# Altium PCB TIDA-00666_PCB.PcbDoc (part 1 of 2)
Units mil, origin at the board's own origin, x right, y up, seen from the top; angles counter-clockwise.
Board outline 1800 x 1650 mil, 4 copper layers (Layer 1 - Top Layer, Layer 2 - GND, Layer 3 - POWER, Layer 4 - Bottom Layer), stack 61.4 mil thick; 112 components, 67 nets, 298 pads, 149 vias.
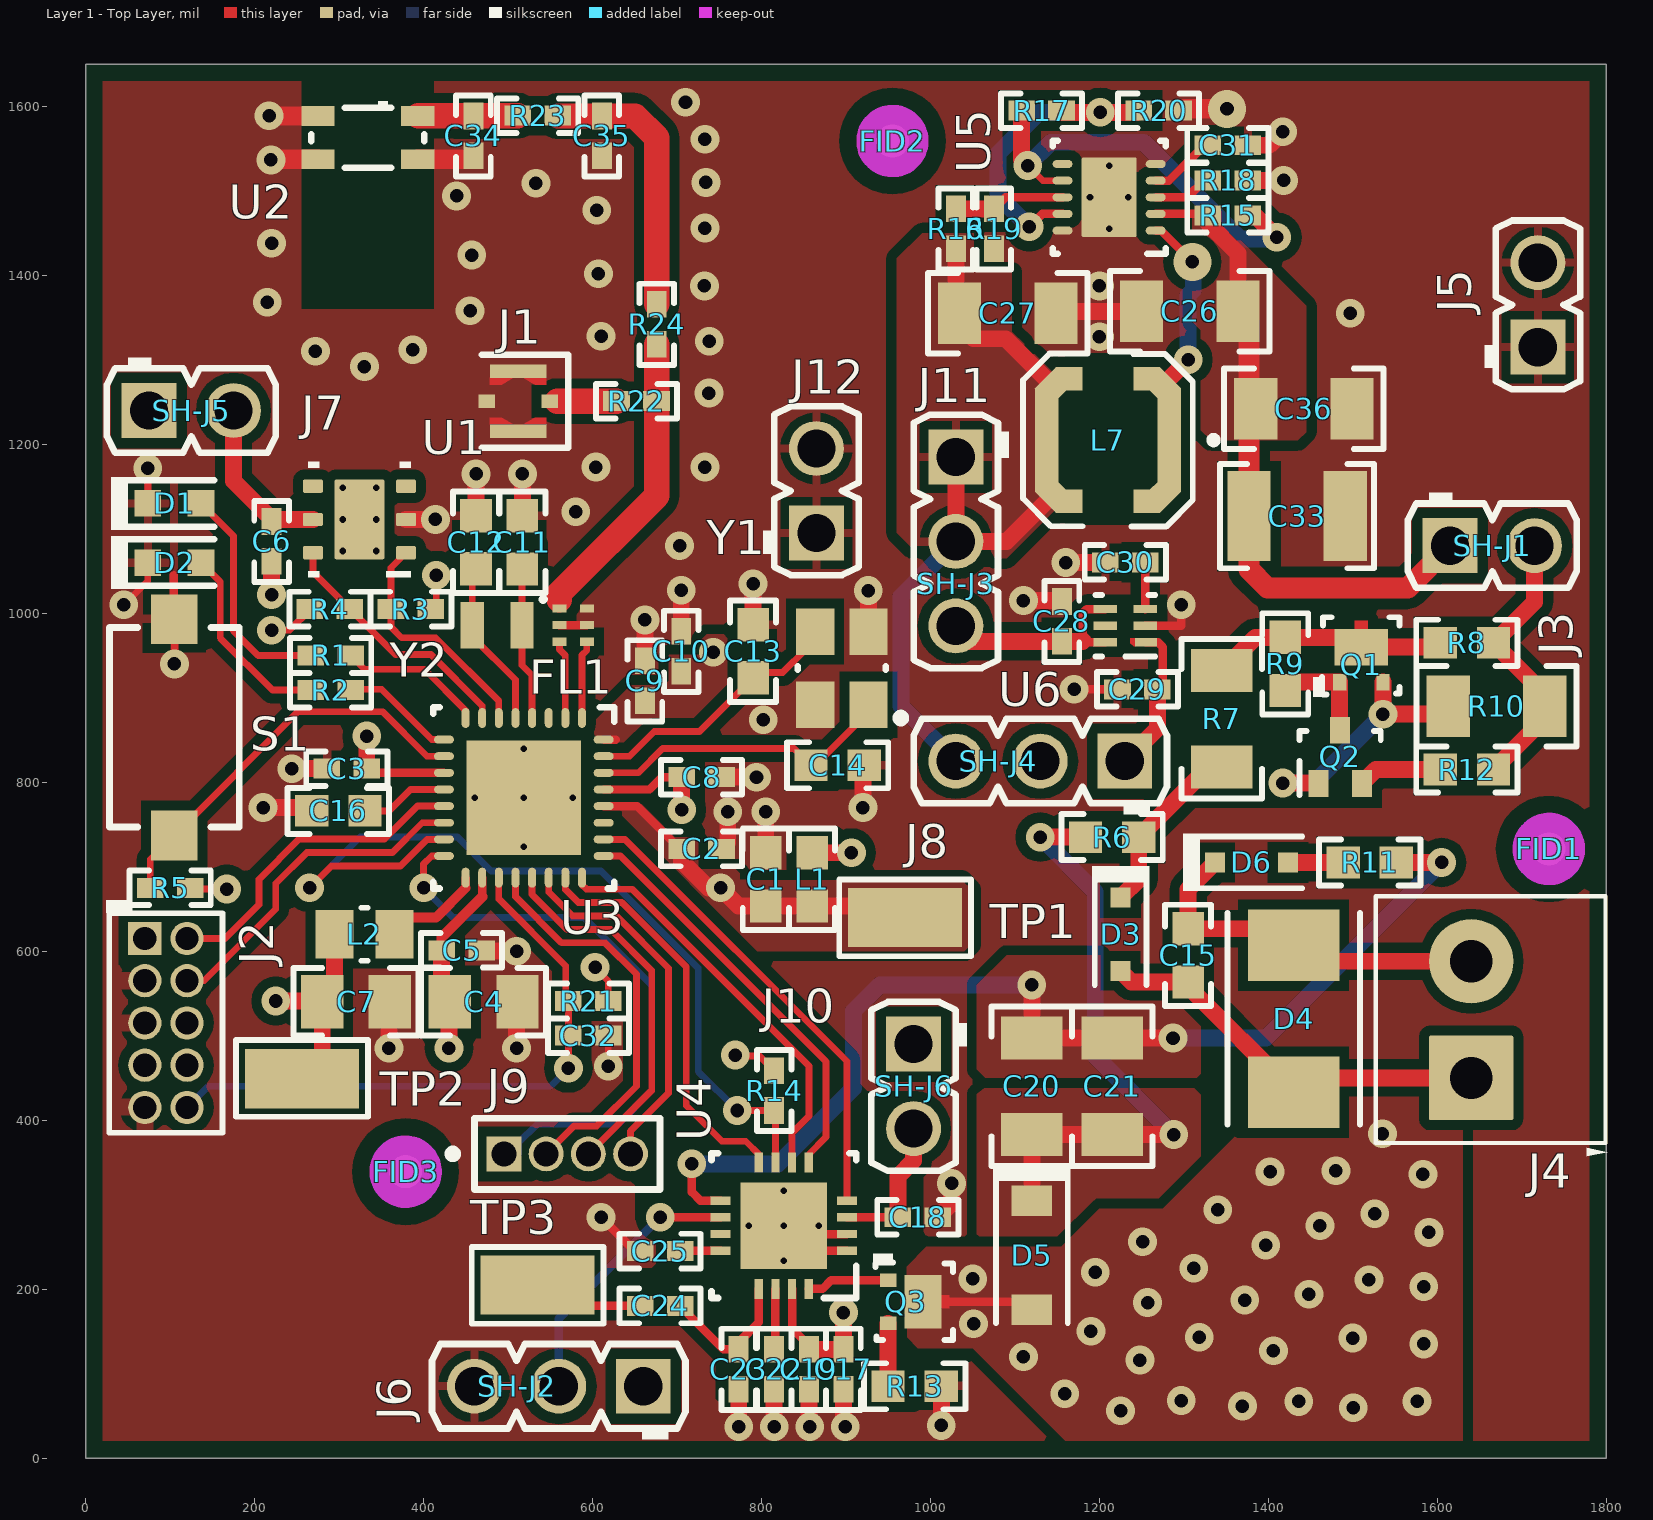
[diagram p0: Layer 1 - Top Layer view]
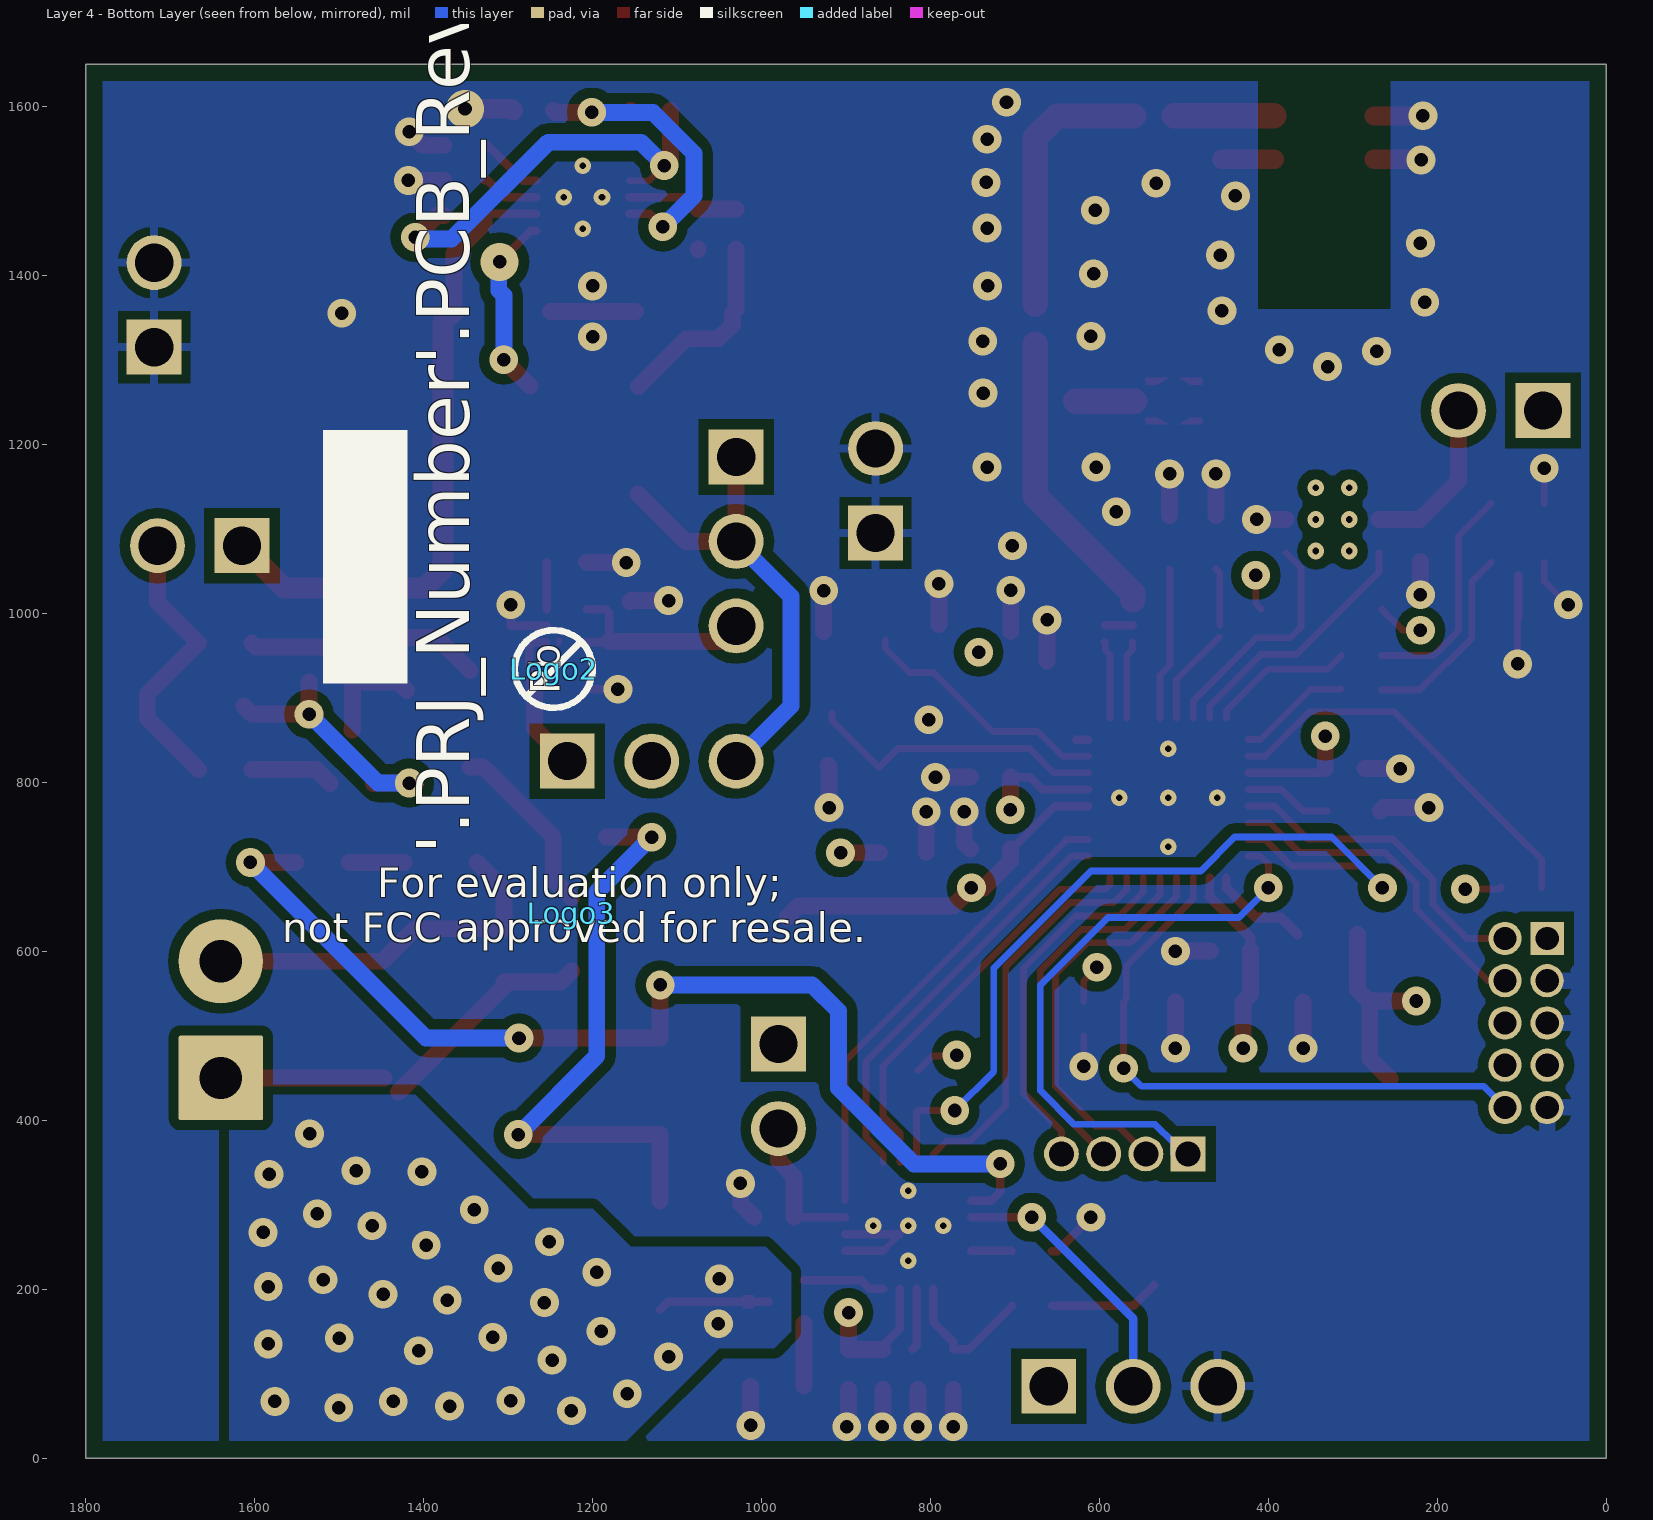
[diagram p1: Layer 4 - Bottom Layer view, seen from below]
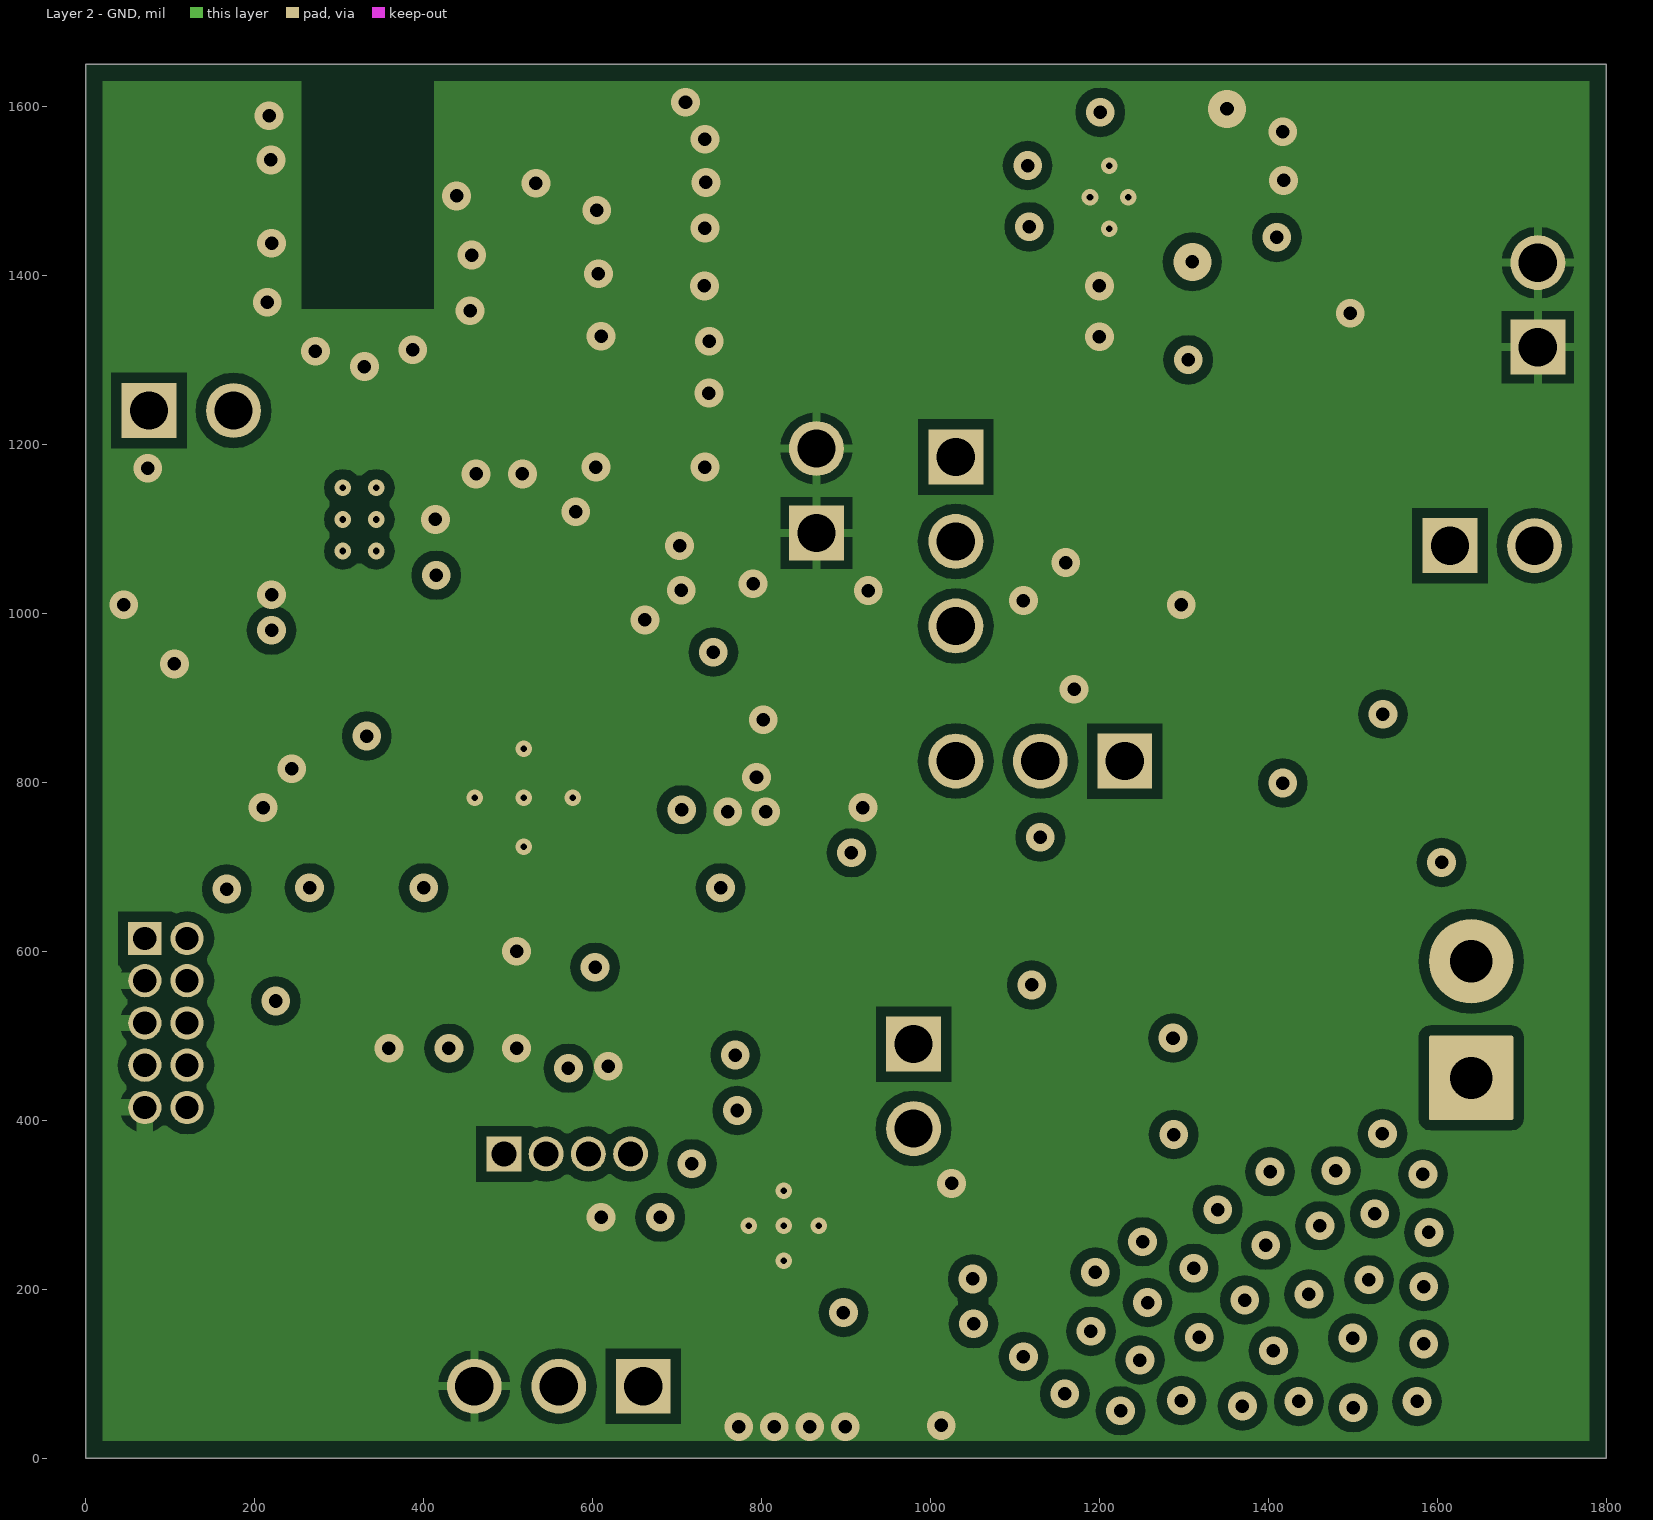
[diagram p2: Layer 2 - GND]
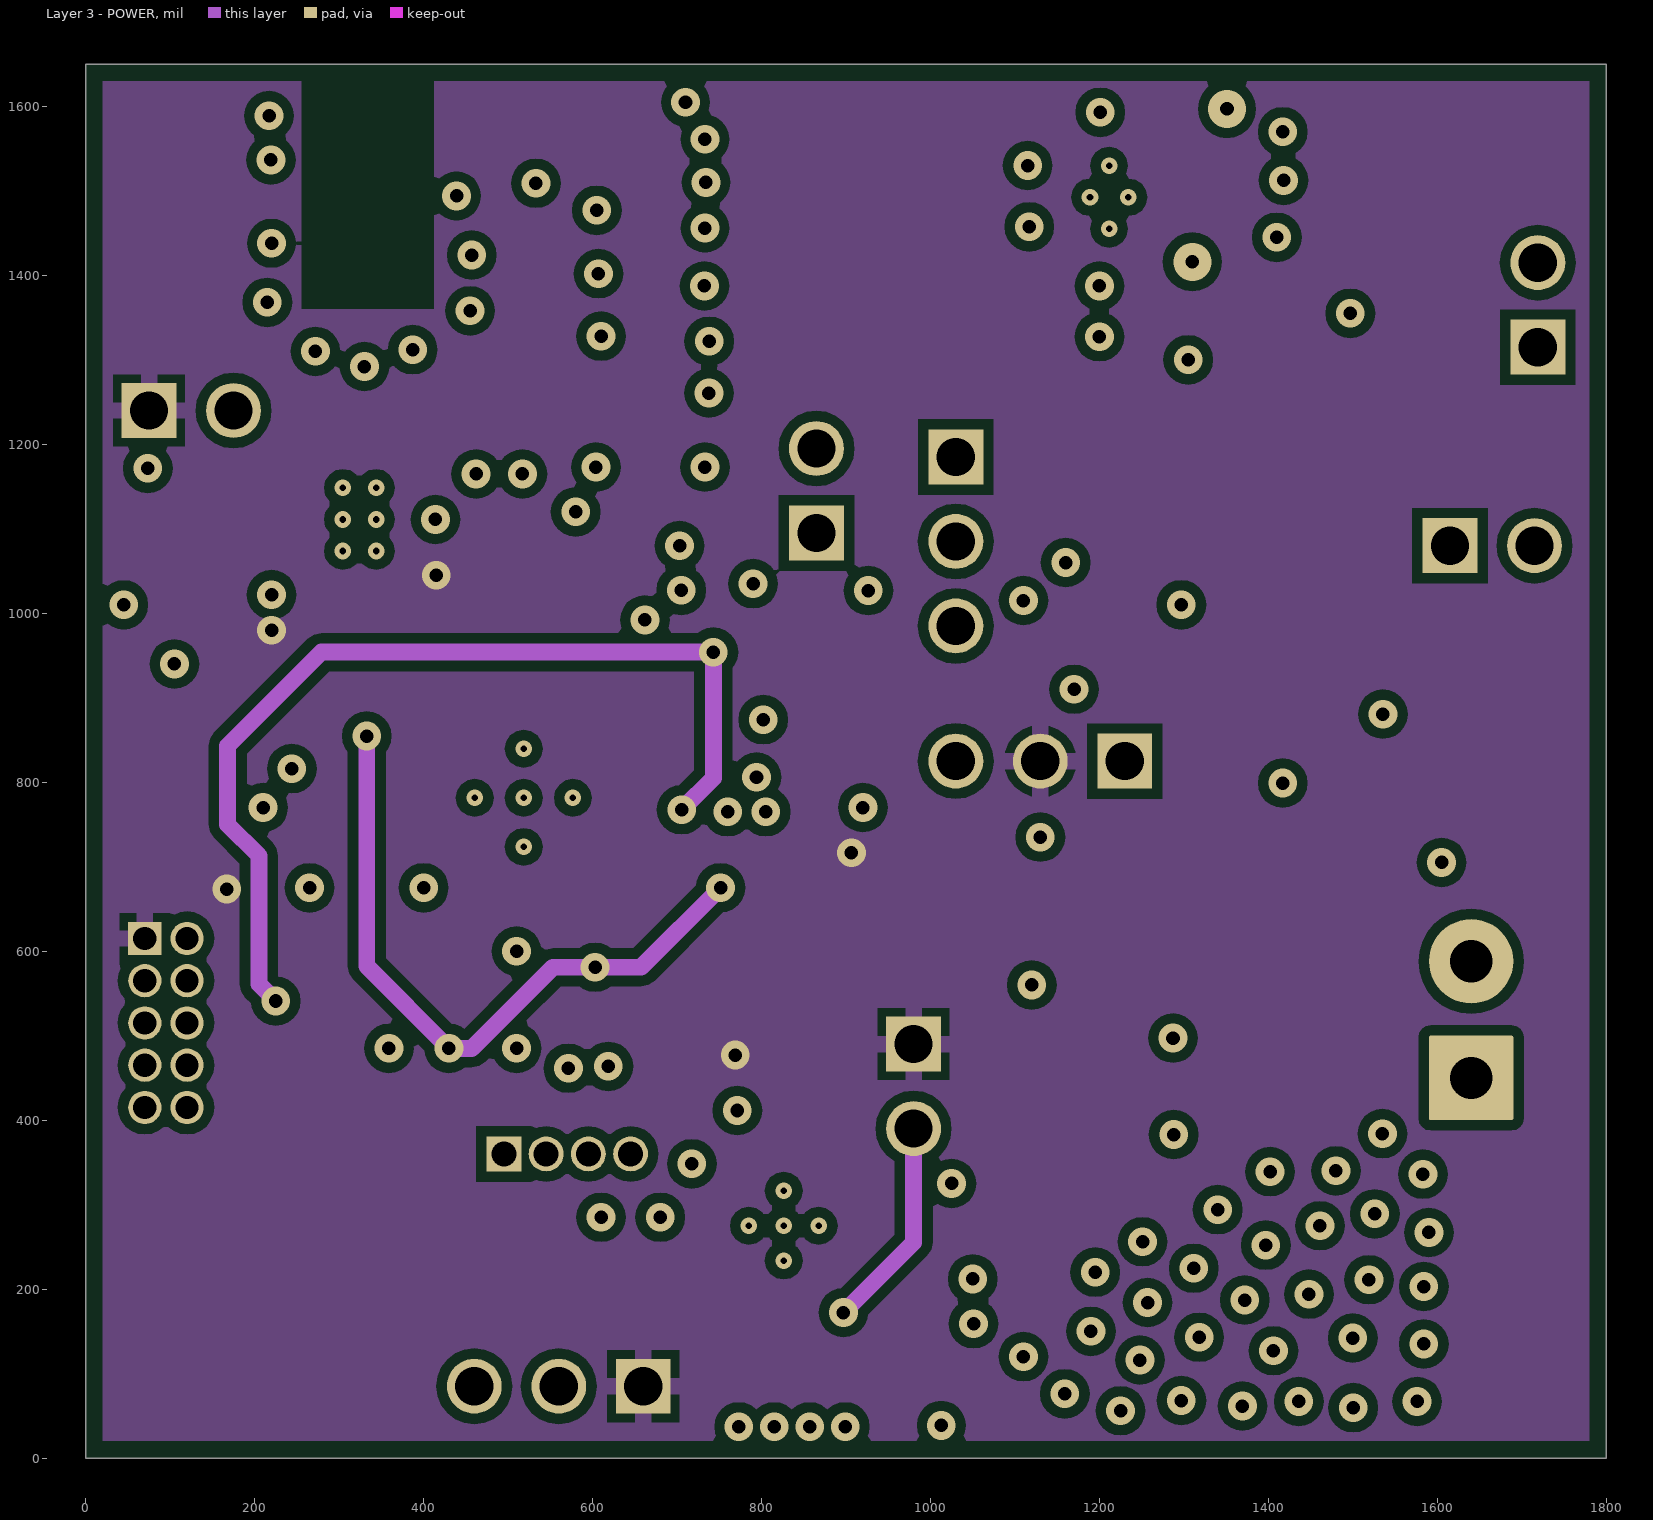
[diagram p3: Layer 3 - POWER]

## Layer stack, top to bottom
Top Solder: solder mask 0.4, Solder Resist, Dk 3.5
Layer 1 - Top Layer: signal copper 1.4
Dielectric1: prepreg 18.6, 370HR, Dk 4.2
Layer 2 - GND: signal copper 1.4
Dielectric3: core 18.6, 370HR, Dk 4.2
Layer 3 - POWER: signal copper 1.4
Dielectric2: prepreg 18.6, 370HR, Dk 4.2
Layer 4 - Bottom Layer: signal copper 1.4
Bottom Solder: solder mask 0.4, Solder Resist, Dk 3.5

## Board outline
0,0 0,1650 1800,1650 1800,0

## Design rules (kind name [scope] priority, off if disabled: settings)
AcuteAngle [All] p1: minimum=4.50000000000000E+0001 checktracksonly=FALSE
AssemblyTestPointUsage [All] p1: valid=2
BoardOutlineClearance BoardOutlineClearance_MountingHoles [OnCopper and InComponentClass('Mounting Holes')] p1: gap=22
BoardOutlineClearance BoardOutlineClearance_Poly [OnCopper and InPoly] p2: gap=20
BoardOutlineClearance [OnCopper and Not InComponentClass('Logo') and not InComponentClass('FiducialMark') and not InRegion(1000,500,4000,800)] p3: gap=20
Clearance Clearance_Keepouts [((IsTrack Or IsArc) And Not InPoly) And IsFree and IsKeepOut vs ((IsTrack Or IsArc) And Not InPoly) And IsFree and IsKeepOut] p1: gap=0
Clearance Clearance_BoardEdge_Poly [OnCopper and InPoly vs IsKeepOut] p2: gap=20
Clearance Clearance_BoardEdge [OnCopper and Not InComponentClass('Logo') and not InComponentClass('FiducialMark') and not InRegion(1000,500,4000,800)and Not IsKeepout vs IsKeepOut] p3: gap=25 except(4: SMDPad-Fill)
Clearance Clearance_Poly [InPolygon] p4: gap=12
Clearance [All] p5: gap=7.87
ComponentClearance ComponentClearance_Header [InComponent('J3') vs InComponent('J5')] p1: gap=10 collisioncheckmode=3 verticalgap=10 showdistances=FALSE
ComponentClearance ComponentClearance_MountingHoles_FiducialMarks [InComponentClass('Mounting Holes') vs InComponentClass('FiducialMark')] p2: gap=40 collisioncheckmode=3 verticalgap=10 showdistances=FALSE
ComponentClearance ComponentClearance_Shunt [InComponentClass('Header') vs InComponentClass('Shunt')] p3: gap=0 collisioncheckmode=3 verticalgap=0 showdistances=FALSE
ComponentClearance ComponentClearance_Logo [InComponentClass('Logo')] p4: gap=10 collisioncheckmode=3 verticalgap=10 showdistances=FALSE
ComponentClearance ComponentClearance_ScrewToNut [(HasFootprint('NY PMS 440 0025 PH')) vs (HasFootprint('Keystone_1902C'))] p5: gap=5 collisioncheckmode=3 verticalgap=10 showdistances=FALSE
ComponentClearance ComponentClearance_MountingHoles [InComponentClass('Mounting Holes')] p6: gap=10 collisioncheckmode=3 verticalgap=100000 showdistances=FALSE
ComponentClearance ComponentClearance_SmallPassives [HasFootprint('0201*') or HasFootprint('0402*') or HasFootprint('0508') or HasFootprint('0603*') or HasFootprint('0612') or HasFootprint('0805*') or HasFootprint('0815*') or HasFootprint('0830*') or HasFootprint('1206*') or HasFootprint('1210*') or HasFootprint('1808*') or HasFootprint('1812*') or HasFootprint('1825*') or HasFootprint('2010*') or HasFootprint('2220*') or HasFootprint('2225*') or HasFootprint('2512*') or HasFootprint('2728*') or HasFootprint('3518*') vs HasFootprint('0201*') or HasFootprint('0402*') or HasFootprint('0508') or HasFootprint('0603*') or HasFootprint('0612') or HasFootprint('0805*') or HasFootprint('0815*') or HasFootprint('0830*') or HasFootprint('1206*') or HasFootprint('1210*') or HasFootprint('1808*') or HasFootprint('1812*') or HasFootprint('1825*') or HasFootprint('2010*') or HasFootprint('2220*') or HasFootprint('2225*') or HasFootprint('2512*') or HasFootprint('2728*') or HasFootprint('3518*')] p7: gap=14.96 collisioncheckmode=3 verticalgap=10 showdistances=FALSE
ComponentClearance ComponentClearance_THtoSMT [IsThruComponent vs IsSMTComponent] p8: gap=20 collisioncheckmode=3 verticalgap=10 showdistances=FALSE
ComponentClearance ComponentClearance_THtoTH [IsThruComponent vs IsThruComponent] p9: gap=40 collisioncheckmode=3 verticalgap=10 showdistances=FALSE
ComponentClearance [All] p10: gap=30 collisioncheckmode=3 verticalgap=10 showdistances=FALSE
DiffPairsRouting [All] p1: maxlimit=100 minlimit=10 mostfreqgap=10 toplayer_minwidth=15 toplayer_maxwidth=15 toplayer_prefwidth=15 midlayer1_minwidth=15 midlayer1_maxwidth=15 midlayer1_prefwidth=15 midlayer2_minwidth=15 midlayer2_maxwidth=15 midlayer2_prefwidth=15 bottomlayer_minwidth=15 bottomlayer_maxwidth=15 bottomlayer_prefwidth=15 maxuncoupledlength=1000
FabricationTestPointUsage TestPointUsage [All] p1: valid=2 allowmultiple=FALSE
FabricationTestpoint Testpoint [All] p1: side=3 testpointundercomponent=TRUE minsize=40 maxsize=100 preferedsize=60 minholesize=0 maxholesize=40 preferedholesize=32 testpointgrid=1 allowsidetop=TRUE allowsidebottom=TRUE usegrid=TRUE gridtolerance=0.01
FanoutControl Fanout_LCC [IsLCC] p1: bgadir=Out bgaviamode=Centered fanoutstyle=Auto fanoutdirection=Alternating viagrid=1 // Fanout_LCC (Default Rule)
FanoutControl Fanout_BGA [IsBGA] p2: bgadir=Out bgaviamode=Centered fanoutstyle=Auto fanoutdirection=Alternating viagrid=1 // Fanout_BGA (Default Rule)
FanoutControl Fanout_Default [All] p4: bgadir=Out bgaviamode=Centered fanoutstyle=Auto fanoutdirection=Alternating viagrid=1 // Fanout_Default (Default Rule)
FanoutControl Fanout_Small [(CompPinCount < 5)] p5: bgadir=Out bgaviamode=Centered fanoutstyle=Auto fanoutdirection=OutThenIn viagrid=1 // Fanout_Small (Default Rule)
HoleSize [All] p1: absolutevalues=TRUE maxlimit=251 minlimit=7.87 maxpercent=80.000 minpercent=20.000
MinimumAnnularRing MinimumAnnularRing_ThermalPad [IsVia and InAnyComponent] p1: minimumring=5.9
MinimumAnnularRing MinimumAnnularRing_J9_J2 [HasPad('J9-*') or HasPad('J2-*')] p2: minimumring=5.9
MinimumAnnularRing [All] p3: minimumring=8
MinimumSolderMaskSliver MinimumSolderMaskSliver_Logo [InComponentClass('Logo') vs InComponentClass('Logo')] p1: minsoldermaskwidth=0.7
MinimumSolderMaskSliver [All] p2: minsoldermaskwidth=3.94
PlaneConnect [All] p1: planeconnectstyle=Direct reliefexpansion=10 reliefentries=4 reliefconductorwidth=10 reliefairgap=10
PolygonConnect PolygonConnect_vccSENSOR [InNet('VCC_SENSOR') vs IsThruPin] p1: connectstyle=Relief reliefconductorwidth=20 reliefentries=4 polygonreliefangle="90 Angle" airgapwidth=10
PolygonConnect PolygonConnect_J2 [All vs InComponent('J2')] p2: connectstyle=Relief reliefconductorwidth=20 reliefentries=4 polygonreliefangle="90 Angle" airgapwidth=10
PolygonConnect PolygonConnect_THT [IsThruPin] p3: connectstyle=Relief reliefconductorwidth=10 reliefentries=4 polygonreliefangle="90 Angle" airgapwidth=10
PolygonConnect PolygonConnect_SMD [InPadClass('PolySMD')] p4: connectstyle=Relief reliefconductorwidth=10 reliefentries=4 polygonreliefangle="90 Angle" airgapwidth=10
PolygonConnect [All] p5: connectstyle=Direct reliefconductorwidth=10 reliefentries=4 polygonreliefangle="90 Angle" airgapwidth=10
RoutingVias ThermalPadVias [IsVia and InAnyComponent] p1: holewidth=7.87 width=19.68 viastyle="Through Hole" minholewidth=7.87 minwidth=19.68 maxholewidth=12.99 maxwidth=23.62
RoutingVias [All] p2: holewidth=16 width=34 viastyle="Through Hole" minholewidth=7.87 minwidth=26 maxholewidth=40 maxwidth=65
ShortCircuit ShortCircuit_ThermalVIA [IsVia vs HasPad('U1-7')] p1: allowed=TRUE
ShortCircuit [All] p2: allowed=FALSE
SilkToBoardRegionClearance [Not ((IsComment or IsDesignator) And (Hide <> 'False')) and not InRegion(1000,500,4000,800)] p1:
SilkToSilkClearance SilkToSilkClearance_Pb-FreeLogo [(HasFootprint('Pb-Free_Overlay_Medium') OR HasFootprint('Pb-Free_Overlay_Small')) vs (HasFootprint('Pb-Free_Overlay_Medium') OR HasFootprint('Pb-Free_Overlay_Small'))] p1: silktosilkclearance=0
SilkToSilkClearance [All] p2: silktosilkclearance=4
SilkToSolderMaskClearance SilkToComponentPadClearance [IsPad and InAnycomponent] p1: minsilkscreentomaskgap=5 clearancetoexposedcopper=TRUE
SilkToSolderMaskClearance "Silk to Solder Mask Opening" [IsPad] p2: minsilkscreentomaskgap=1 clearancetoexposedcopper=TRUE
SolderMaskExpansion [All] p1: expansion=1.97
Width [All] p1: maxlimit=100 minlimit=6 preferedwidth=10 checkconnectedcopper=TRUE
14 further rules are at their usual default settings.

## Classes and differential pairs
component class TIDA-00666_Hardware: FID1 FID2 FID3 Logo2 Logo3 ZZ1 ZZ2 ZZ3 ZZ4
component class FiducialMark: FID1 FID2 FID3
component class AssemblyNote: ZZ1 ZZ2 ZZ3 ZZ4
component class Header: J2 J3 J5 J6 J7 J8 J9 J10 J11 J12
component class Shunt: SH-J1 SH-J2 SH-J3 SH-J4 SH-J5 SH-J6
component class TIDA-00666_DAC: C15 C17 C18 C19 C20 C21 C22 C23 C24 C25 D3 D4 D5 D6 J3 J4 J5 J6 J10 Q1 Q2 Q3 R6 R7 R8 R9 R10 R11 R12 R13 R14 SH-J1 SH-J2 SH-J6 TP3 U4
component class TIDA-00666_MCU: C1 C2 C3 C4 C5 C6 C7 C8 C9 C10 C11 C12 C13 C14 C16 C32 C34 C35 D1 D2 FL1 J1 J2 J7 J9 L1 L2 R1 R2 R3 R4 R5 R21 R22 R23 R24 S1 SH-J5 TP1 TP2 U1 U2 U3 Y1 Y2
component class TIDA-00666_Power: C26 C27 C28 C29 C30 C31 C33 C36 J8 J11 J12 L7 R15 R16 R17 R18 R19 R20 SH-J3 SH-J4 U5 U6
pad class PolySMD: C3-2 C11-1 C12-2 C13-2 C14-2 C16-2 C29-2 C30-2 C31-2 D1-1 D2-1 R13-1 R18-1 S1-2

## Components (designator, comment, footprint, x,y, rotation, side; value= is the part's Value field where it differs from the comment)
C1 "Used in BOM report" 0603 805,685 r90 top
C2 "GRM155R70J104KA01D" 0402 729.06,721.02 r0 top
C3 "GRM155R70J104KA01D" 0402 309.05,816.02 r180 top
C4 "GRM21BR70J106KE76L" 0805_HV 471,540 r0 top
C5 "GRM155R70J104KA01D" 0402 445,601 r0 top
C6 "GRM155R70J104KA01D" 0402 220,1085 r270 top
C7 "GRM21BR70J106KE76L" 0805_HV 320,540 r0 top
C8 "GRM155R70J104KA01D" 0402 729.06,806.02 r0 top
C9 "GRM155R70J104KA01D" 0402 662,920 r90 top
C10 "Used in BOM report" 0402 705,955 r90 top
C11 "06035A120JAT2A" 0603 517,1084 r270 top
C12 "06035A120JAT2A" 0603 462.06,1084.02 r90 top
C13 "Used in BOM report" 0603 790,955 r90 top
C14 "Used in BOM report" 0603 890,820 r0 top
C15 "C1608X7R2A103K" 0603 1305,595 r90 top
C16 "GRM188R70J105KA01D" 0603 299.05,766.02 r180 top
C17 "C1005X5R1C225K050BC" 0402 897,105 r270 top
C18 "C1005X5R0J104K" 0402 985,285 r0 top
C19 "C1005X5R0J104K" 0402 856,105 r270 top
C20 "12061C104JAT2A" 1206 1120,440 r90 top
C21 "GRM31CR72A105KA01L" 1206 1215,440 r90 top
C22 "GRM155R61A394KE15D" 0402 815,105 r270 top
C23 "GRM155R60J224KE01D" 0402 773,105 r270 top
C24 "GRM155R71E682KA01D" 0402 680,180 r180 top
C25 "GRM155R60J102KA01D" 0402 680,245 r180 top
C26 "GRM31CR72A105KA01L" 1206 1306.96,1357.4 r180 top
C27 "GRM31CR71A226KE15L" 1206 1091.46,1355 r0 top
C28 "C1005X7S1A105K050BC" 0402 1155.59,990.32 r90 top
C29 "C1005X7S1A105K050BC" 0402 1245,910 r180 top
C30 "C1005X7R1C103K050BA" 0402 1230.59,1060.32 r180 top
C31 "GRM155R71C473KA01D" 0402 1352,1554 r0 top
C32 "GRM155R70J104KA01D" 0402 595,500 r0 top
C33 "GRM32ER71J106KA12L" 1210_270 1434,1115 r0 top
C34 "Used in BOM report" 0402 459,1565 r270 top
C35 "Used in BOM report" 0402 611,1565 r270 top
C36 "UMK316B7225KL-T" 1206 1442,1242 r0 top
D1 "150060VS75000" WL-SMCW_GREEN 105,1130 r0 top
D2 "150060SS75000" WL-SMCW_RED 105,1060 r0 top
D3 "BAT46WJ,115" SOD-323F 1225,620 r270 top
D4 "SM6T39CA" SMB-Bi 1430,520 r90 top
D5 "MMSZ4686T1G" SOD-123 1120,240 r270 top
D6 "BAT46WJ,115" SOD-323F 1380,705 r0 top
FID1 "Fiducial" Fiducial10-20 1732,721 r0 top
FID2 "Fiducial" Fiducial10-20 955,1559 r0 top
FID3 "Fiducial" Fiducial10-20 378.68,338.96 r0 top
FL1 "LFB182G45BG5D920" Murata_LFB182G45BG5D920 577,986.02 r0 top
J1 "MM5829-2700RJ4" MuRata_MM5829-2700 512,1251 r270 top
J2 "GRPB052VWVN-RC" CONN_GRPB052VWVN-RC 95,515 r270 top
J3 "61300211121" WURTH_61300211121 1665,1080 r0 top
J4 "ED555/2DS" TERM_BLK_ED555-2DS 1640,450 r90 top
J5 "61300211121" WURTH_61300211121 1719,1365 r90 top
J6 "61300311121" WURTH_61300311121 560,85 r180 top
J7 "61300211121" WURTH_61300211121 125,1240 r0 top
J8 "61300311121" WURTH_61300311121 1130,825 r180 top
J9 "GRPB041VWVN-RC" Sullins_GRPB041VWVN-RC 570,360 r0 top
J10 "61300211121" WURTH_61300211121 980,440 r270 top
J11 "61300311121" WURTH_61300311121 1030,1085 r270 top
J12 "61300211121" WURTH_61300211121 865,1145 r90 top
L1 "BLM18HE152SN1D" 0603 860,685 r90 top
L2 "CKS2125100M-T" 0805_145 330,620 r180 top
L7 "LPS4018-184MLB" LPS4018 1210,1205 r180 top
Logo2 "Pb-Free Symbol" Pb-Free_Overlay_Small 1246,934 r90 bottom
Logo3 "FCC disclaimer" FCC_disclaimer_stacked 1225,645 r180 bottom
Q1 "BC55-16PA,115" SOT1061 1510,950 r90 top
Q2 "MMSTA06-7-F" SOT-323 1485,830 r90 top
Q3 "BC55-16PA,115" SOT1061 981.34,185 r0 top
R1 "CRCW0402470RJNED" 0402 290,950 r0 top
R2 "CRCW0402470RJNED" 0402 290,909 r180 top
R3 "CRCW040210K0FKED" 0402 385,1005 r0 top
R4 "CRCW040210K0FKED" 0402 289,1005 r180 top
R5 "CRCW040247K5FKED" 0402 100,675 r0 top
R6 "CRCW06030000Z0EA" 0603 1215,735 r180 top
R7 "CRCW1206200RFKEA" 1206 1345,875 r90 top
R8 "CRCW06030000Z0EA" 0603 1635,965 r0 top
R9 "CRCW060324K9FKEA" 0603 1420,940 r90 top
R10 "CRCW120649R9FKEA" 1206 1670,890 r180 top
R11 "CRCW06030000Z0EA" 0603 1520,705 r180 top
R12 "CRCW0603100RFKEA" 0603 1635,815 r180 top
R13 "CRCW060320R0FKEA" 0603 981.34,85 r180 top
R14 "CRCW04021M00JNED" 0402 815,435 r270 top
R15 "CRCW04022M00FKED" 0402 1352,1471 r180 top
R16 "CRCW0402499KFKED" 0402 1030,1455 r270 top
R17 "CRCW0402357KFKED" 0402 1131.46,1595 r180 top
R18 "CRCW0402100KFKED" 0402 1351.96,1512.4 r180 top
R19 "CRCW0402294KFKED" 0402 1075,1455 r90 top
R20 "CRCW040234K0FKED" 0402 1270,1595 r180 top
R21 "CRCW040247K5FKED" 0402 595,541 r0 top
R22 "CRCW04020000Z0ED" 0402 652,1251 r180 top
R23 "CRCW04020000Z0ED" 0402 535,1589 r180 top
R24 "CRCW04020000Z0ED" 0402 676,1342 r270 top
S1 "434121025816" SW_434121025816 105,865 r90 top
SH-J1 "969102-0000-DA" SNT-100-BK-G 1665.01,1080.01 r180 top
SH-J2 "969102-0000-DA" SNT-100-BK-G 510,85 r180 top
SH-J3 "969102-0000-DA" SNT-100-BK-G 1030.01,1034.99 r90 top
SH-J4 "969102-0000-DA" SNT-100-BK-G 1080,825 r180 top
SH-J5 "969102-0000-DA" SNT-100-BK-G 125,1239.96 r180 top
SH-J6 "969102-0000-DA" SNT-100-BK-G 979.96,440 r90 top
TP1 "5015" Testpoint_Keystone_Miniature 970,640 r0 top
TP2 "5015" Testpoint_Keystone_Miniature 255.93,449.02 r180 top
TP3 "5015" Testpoint_Keystone_Miniature 535,205 r0 top
U1 "HDC1080DMBR" DMB0006A 324.05,1111.02 r180 top
U2 "2450AT18D0100E" JohansonTech_2450AT18D0100E 334,1563 r270 top
U3 "CC2650F128RHBR" RHB0032E 518.58,781.54 r270 top
U4 "DAC161S997RGHR" RGH0016A 826.34,275 r180 top
U5 "LM5165DRCR" DRC0010J 1211.46,1492.4 r180 top
U6 "TPS71728DSER" DSE0006A 1230.59,985.32 r180 top
Y1 "TSX-3225 24.0000MF20G-AC3" EPSON_TSX-3225 895,935 r180 top
Y2 "FC-12M 32.7680KA-A3" Epson_FC-12M 487,986 r180 top
ZZ1 "This Assembly Note is for PCB labels only" AssemblyNoteLabel 185,3938 r0 top
ZZ2 "This Assembly Note will show in the PcbDoc and associated outputs" AssemblyNote 185,3829.11 r0 top
ZZ3 "This Assembly Note will show in the PcbDoc and associated outputs" AssemblyNote 185,3740.56 r0 top
ZZ4 "This Assembly Note will show in the PcbDoc and associated outputs" AssemblyNote 185,3652 r0 top

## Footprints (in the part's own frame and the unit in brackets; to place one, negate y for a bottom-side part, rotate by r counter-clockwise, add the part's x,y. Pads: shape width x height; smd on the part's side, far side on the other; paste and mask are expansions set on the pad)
0402 [mm] "0402 from SM-752 data"
  rect 0.8x0.6 smd: 1(-0.6,0) 2(0.6,0)
  silkscreen extent -1.22,-0.52 1.22,0.52, body extent -0.55,-0.3 0.55,0.3, height 0.6
0603 [mm] "0603 from SM-752 data"
  rect 1x0.95 smd: 1(-0.8,0) 2(0.8,0)
  silkscreen extent -1.52,-0.69 1.52,0.69, body extent -0.87,-0.47 0.87,0.47, height 1
0805_145 [mm] "0805 / 1.45mm height"
  rect 1.15x1.45 smd: 1(-0.9,0) 2(0.9,0)
  silkscreen extent -0.1,-0.8 0.1,0.8, body extent -1.1,-0.72 1.1,0.72, height 1.45
0805_HV [mil] "0805 with 30mil clearance between pads"
  rect 50x63 smd: 1(-40,0) 2(40,0)
  silkscreen extent -74,-40 74,40, body extent -43,-29 43,29, height 57
1206 [mm] "1206 from SM-752 data"
  rect 1.3x1.85 smd: 1(-1.45,0) 2(1.45,0)
  silkscreen extent -2.4,-1.21 2.4,1.21, body extent -1.7,-0.9 1.7,0.9, height 1.35
1210_270 [mm] "1210"
  rect 1.3x2.7 smd: 1(-1.45,0) 2(1.45,0)
  silkscreen extent -2.32,-1.57 2.32,1.57, body extent -1.7,-1.35 1.7,1.35, height 2.7
AssemblyNote [mil] "Assembly Note"
AssemblyNoteLabel [mil] "Assembly Note for PCB Labels"
CONN_GRPB052VWVN-RC [mm] "SULLINS"
  rect 1x1 hole 0.7 mask+0.08: 1(-2.54,-0.635)
  round 1 hole 0.7 mask+0.08: 2(-2.54,0.635) 3(-1.27,-0.635) 4(-1.27,0.635) 5(0,-0.635) 6(0,0.635) 7(1.27,-0.635) 8(1.27,0.635) 9(2.54,-0.635) 10(2.54,0.635)
  silkscreen extent -3.7,-1.8 3.3,1.7, body extent -3.17,-1.7 3.17,1.7, height 4
DMB0006A [mm] "TI"
  rrect25% 0.6x0.4 smd: 1(-1.4,1) 2(-1.4,0) 3(-1.4,-1) 4(1.4,-1) 5(1.4,0) 6(1.4,1)
  rrect7% 1.5x2.4 smd paste-0.75: 7(0,0)
  silkscreen extent -1.55,-1.75 1.55,1.75, body extent -1.5,-1.5 1.5,1.5, height 0.81
DRC0010J [mm] "SON, 10-Leads, Body 3x3mm, Pitch 0.5mm, Thermal Pad 2.4x1.65mm, TI Recommended"
  rrect100% 0.6x0.24 smd: 1(-1.4,1) 2(-1.4,0.5) 3(-1.4,0) 4(-1.4,-0.5) 5(-1.4,-1) 6(1.4,-1) 7(1.4,-0.5) 8(1.4,0) 9(1.4,0.5) 10(1.4,1)
  rrect6% 1.65x2.4 smd paste-0.825: 11(0,0)
  silkscreen extent -1.7,-1.7 1.7,1.7, body extent -1.5,-1.5 1.5,1.5, height 0.77
DSE0006A [mm] "TI recommended land pattern"
  rect 0.66x0.25 smd: 1(-0.62,0.5)
  rect 0.7x0.25 smd: 2(-0.6,0) 3(-0.6,-0.5) 4(0.6,-0.5) 5(0.6,0) 6(0.6,0.5)
  Layer 1 - Top Layer region: -0.3,0.625 -0.25,0.625 -0.15,0.525 -0.15,0.375 -0.3,0.375
  silkscreen extent -0.9,-0.92 0.9,0.92, body extent -0.77,-0.77 0.77,0.77, height 0.8
Epson_FC-12M [mm] "Epson"
  rect 0.7x1.4 smd: 1(-0.75,0) 2(0.75,0)
  body extent -1.05,-0.63 1.05,0.63, height 0.6
EPSON_TSX-3225 [mm] "SMD, 4-Leads, Body 2.65x3.35mm, Height 0.6mm"
  rect 1.15x1.4 smd: 1(-0.8,1.1) 2(-0.8,-1.1) 3(0.8,-1.1) 4(0.8,1.1)
  silkscreen extent -1.9,-0.05 1.33,1.62, body extent -1.33,-1.68 1.33,1.68, height 0.61
FCC_disclaimer_stacked [mil]
Fiducial10-20 [mm]
  round 1 smd mask+0.5: 1(0,0)
  Layer 1 - Top Layer keep-out circle w1.178: c0,0 r0.5
JohansonTech_2450AT18D0100E [mm] "SMD, 4-Leads, Body 3.2x1.6mm"
  rect 0.6x1 smd: 1(-0.65,1.5) 2(-0.65,-1.5) 3(0.65,-1.5) 4(0.65,1.5)
  silkscreen extent -1.1,-1.7 0.9,1.7, body extent -0.9,-1.7 0.9,1.7, height 1.4
LPS4018 [mil]
  rect 28x123 smd: 1(-72.5,0) 2(72.5,0)
  rect 35.5x28 smd rot 45: 1(-64,64) 2(64.5,-63.5)
  rect 35.5x28 smd rot 135: 1(-64,-64) 2(64,64)
  rect 31.5x28 smd: 1(-46,72.5) 1(-46,-72.5) 2(46,72.5) 2(46,-72.5)
  silkscreen extent -129,-102 101,102, body extent -81,-81 81,81, height 71
Murata_LFB182G45BG5D920 [mm] "SMT, 6-Leads, Body 1.6x0.8mm, Pitch 0.5mm"
  rect 0.425x0.25 smd mask+0.07: 1(-0.413,0.5) 2(-0.413,0) 3(-0.413,-0.5) 4(0.412,-0.5) 5(0.412,0) 6(0.412,0.5)
  silkscreen extent -0.91,0.77 -0.89,0.78, body extent -0.45,-0.85 0.45,0.85, height 0.65
MuRata_MM5829-2700 [mm] "Connector, RF, SMT"
  rect 0.4x0.5 smd paste-1.7 mask-1.7: 1(0,0.95) 2(0,-0.95)
  rect 0.4x1.7 smd paste-1.7 mask-1.7: 2(-0.9,0) 2(0.9,0)
  Layer 1 - Top Layer region: -0.5,-0.85 -0.5,-0.5 -0.7,-0.15 -0.7,-0.85
  Layer 1 - Top Layer region: -0.5,0.85 -0.5,0.5 -0.7,0.15 -0.7,0.85
  Layer 1 - Top Layer region: 0.5,0.85 0.5,0.5 0.7,0.15 0.7,0.85
  Layer 1 - Top Layer region: 0.5,-0.85 0.5,-0.5 0.7,-0.15 0.7,-0.85
  silkscreen extent -1.4,-1.1 1.4,1.5, body extent -0.9,-1 0.9,1, height 0.5
Pb-Free_Overlay_Small [mil]
  silkscreen extent -46,-46 46,46
RGH0016A [mm] "QFN, 16-Leads, Body 4x4mm, Pitch 0.5mm, TI Recommended"
  rect 0.6x0.25 smd: 1(-1.9,0.75) 2(-1.9,0.25) 3(-1.9,-0.25) 4(-1.9,-0.75) 9(1.9,-0.75) 10(1.9,-0.25) 11(1.9,0.25) 12(1.9,0.75)
  rect 0.25x0.6 smd: 5(-0.75,-1.9) 6(-0.25,-1.9) 7(0.25,-1.9) 8(0.75,-1.9) 13(0.75,1.9) 14(0.25,1.9) 15(-0.25,1.9) 16(-0.75,1.9)
  rect 2.6x2.6 smd paste-1.3: 17(0,0)
  silkscreen extent -2.17,-2.17 2.17,2.17, body extent -2.05,-2.05 2.05,2.05, height 0.81
RHB0032E [mm] "QFN, 32-Leads, Body 5x5mm, Pitch 0.5mm, Thermal Pad 3.45x3.45mm, TI Recommended"
  oval 0.6x0.24 smd: 1(-2.4,1.75) 2(-2.4,1.25) 3(-2.4,0.75) 4(-2.4,0.25) 5(-2.4,-0.25) 6(-2.4,-0.75) 7(-2.4,-1.25) 8(-2.4,-1.75) 17(2.4,-1.75) 18(2.4,-1.25) 19(2.4,-0.75) 20(2.4,-0.25) 21(2.4,0.25) 22(2.4,0.75) 23(2.4,1.25) 24(2.4,1.75)
  oval 0.24x0.6 smd: 9(-1.75,-2.4) 10(-1.25,-2.4) 11(-0.75,-2.4) 12(-0.25,-2.4) 13(0.25,-2.4) 14(0.75,-2.4) 15(1.25,-2.4) 16(1.75,-2.4) 25(1.75,2.4) 26(1.25,2.4) 27(0.75,2.4) 28(0.25,2.4) 29(-0.25,2.4) 30(-0.75,2.4) 31(-1.25,2.4) 32(-1.75,2.4)
  rect 3.45x3.45 smd paste-1.725: 33(0,0)
  silkscreen extent -2.72,-2.73 2.72,2.73, body extent -2.57,-2.57 2.58,2.58, height 1.01
SMB-Bi [mil] "Molded Diode, 2-Leads, Body 5.4x3.6mm, IPC Medium Density, based on OnSemi component dimensions"
  rect 85x107.99 smd: 1(-87.01,0) 2(87.01,0)
  silkscreen extent -125,-79 125,79, body extent -104,-73 104,73, height 89
SNT-100-BK-G [mil] "Samtec STEP model"
  round 1 on Mech3: 0(0,0)
  body extent -100,-50 100,50, height 344
SOD-123 [mm] "On Semi recommended land pattern"
  rect 0.915x1.22 smd: 1(-1.637,0) 2(1.637,0)
  silkscreen extent -2.74,-1.17 2.03,1.17, body extent -1.93,-0.9 1.93,0.9, height 1.35
SOD-323F [mm] "NXP recommended land pattern"
  rect 0.6x0.6 smd paste-0.05: 1(-1.1,0) 2(1.1,0)
  silkscreen extent -2.06,-0.86 1.53,0.86, body extent -1.35,-0.67 1.35,0.68, height 0.79
SOT1061 [mm] "NXP SEMICONDUCTOR (HUSON3)"
  rect 0.5x0.4 smd mask+0.05: 1(-0.8,0.65) 2(-0.8,-0.65)
  rect 1.1x1.6 smd mask+0.05: 3(0.25,0)
  Layer 1 - Top Layer region: 1.05,-0.2 1.05,0.2 0.7,0.2 0.7,-0.2
  silkscreen extent -1.25,-1.15 1.15,1.45, body extent -1.05,-1.05 1.05,1.05, height 0.66
SOT-323 [mm] "Zetex recommended land pattern.  March 2007"
  rect 0.8x0.6 smd: 1(-0.8,0.65) 2(-0.8,-0.65) 3(0.8,0)
  silkscreen extent -1.14,-1.22 0.77,1.22, body extent -1.13,-1.13 1.12,1.12, height 1.13
Sullins_GRPB041VWVN-RC [mm] "TH, Header, 1.27 mm, 4x1, Straight"
  rect 1.05x1.05 hole 0.75: 1(-1.905,0)
  round 1.05 hole 0.75: 2(-0.635,0) 3(0.635,0) 4(1.905,0)
  silkscreen extent -3.54,-1.07 2.79,1.07, body extent -2.79,-1.07 2.79,1.07, height 4.3
SW_434121025816 [mm] "SMD, 2-Leads, Body 6x3.9mm, Pitch 6.5mm"
  rect 1.5x1.4 smd: 1(-3.25,0) 2(3.25,0)
  silkscreen extent -3,-1.95 3,1.95, body extent -3.65,-1.95 3.65,1.95, height 2.5
TERM_BLK_ED555-2DS [mil]
  rrect4% 100x100 hole 50: 1(0,0)
  round 100 hole 50: 2(138,0)
  silkscreen extent -93,-161 215,113, body extent -69,-150 207,106, height 323
Testpoint_Keystone_Miniature [mil] "Miniature SMT test point"
  rect 135x70 smd: 1(0,0)
  silkscreen extent -78,-46 78,45, body extent -52,-20 52,20, height 61
WL-SMCW_GREEN [mm] "WURTH"
  rect 0.8x0.8 smd: 1(-0.8,0) 2(0.8,0)
  silkscreen extent -1.9,-0.8 1.2,0.8, body extent -0.85,-0.45 0.85,0.45, height 0.8
WL-SMCW_RED [mm] "WURTH"
  rect 0.8x0.8 smd: 1(-0.8,0) 2(0.8,0)
  silkscreen extent -1.9,-0.8 1.2,0.8, body extent -0.85,-0.45 0.85,0.45, height 0.8
WURTH_61300211121 [mm] "Header, 2.54mm, 2x1, TH"
  rect 1.65x1.65 hole 1.15: 1(-1.27,0)
  round 1.65 hole 1.15: 2(1.27,0)
  silkscreen extent -2.54,-1.27 2.54,1.6, body extent -2.54,-1.27 2.54,1.27, height 8.54
WURTH_61300311121 [mm] "Header, 2.54mm, 3x1, TH"
  rect 1.65x1.65 hole 1.15: 1(-2.54,0)
  round 1.65 hole 1.15: 2(0,0) 3(2.54,0)
  silkscreen extent -3.81,-1.27 3.81,1.6, body extent -3.81,-1.27 3.81,1.27, height 8.54

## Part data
C1 C10 C13 C14 C34 C35: library part Capacitor, "CAP, CERM, xxxF, xxV, [TempCo], xx%, [PackageReference]"
C2 C3 C5 C6 C8 C9 C32: "CAP, CERM, 0.1 µF, 6.3 V, +/- 10%, X7R, 0402"
C4 C7: "CAP, CERM, 10 µF, 6.3 V, +/- 10%, X7R, 0805"
C11 C12: "CAP, CERM, 12 pF, 50 V, +/- 5%, C0G/NP0, 0603"
C15: "CAP, CERM, 0.01 µF, 100 V, +/- 10%, X7R, 0603"
C16: "CAP, CERM, 1 µF, 6.3 V, +/- 10%, X7R, 0603"
C17: "CAP, CERM, 2.2 µF, 16 V, +/- 10%, X5R, 0402"
C18 C19: "CAP, CERM, 0.1 µF, 6.3 V, +/- 10%, X5R, 0402"
C20: "CAP, CERM, 0.1 µF, 100 V, +/- 5%, X7R, 1206"
C21 C26: "CAP, CERM, 1 µF, 100 V, +/- 10%, X7R, 1206"
C22: "CAP, CERM, 0.39 µF, 10 V, +/- 10%, X5R, 0402"
C23: "CAP, CERM, 0.22 µF, 6.3 V, +/- 10%, X5R, 0402"
C24: "CAP, CERM, 6800 pF, 25 V, +/- 10%, X7R, 0402"
C25: "CAP, CERM, 1000 pF, 6.3 V, +/- 10%, X5R, 0402"
C27: "CAP, CERM, 22 µF, 10 V, +/- 10%, X7R, 1206"
C28 C29: "CAP, CERM, 1 µF, 10 V, +/- 10%, X7S, 0402"
C30: "CAP, CERM, 0.01 µF, 16 V, +/- 10%, X7R, 0402"
C31: "CAP, CERM, 0.047 µF, 16 V, +/- 10%, X7R, 0402"
C33: "CAP, CERM, 10 µF, 63 V, +/- 10%, X7R, 1210"
C36: "CAP, CERM, 2.2 µF, 50 V, +/- 10%, X7R, 1206"
D1: "LED, Green, SMD"
D2: "LED, Super Red, SMD"
D3 D6: "Diode, Schottky, 100 V, 0.25 A, SOD-323F"
D4: "Diode, TVS, Bi, 39 V, 600 W, SMB"
D5: "Diode, Zener, 3.9 V, 500 mW, SOD-123"
FID1 FID2 FID3: "Fiducial mark.  There is nothing to buy or mount."
FL1: "Filter, BandPass, 2.45GHz, SMD"
J1: "Connector, RF, 50 Ohm, SMT"
J2: "Header, 50mil, 5x2, Gold, TH"
J3 J5 J7 J10 J12: "Header, 2.54 mm, 2x1, Gold, TH"
J4: "Terminal Block, 3.5mm Pitch, 2x1, TH"
J6 J8 J11: "Header, 2.54 mm, 3x1, Gold, TH"
J9: "Header, 50mil, 4x1, Gold, TH"
L1: "Ferrite Bead, 1500 ohm @ 100 MHz, 0.5 A, 0603"
L2: "Inductor, Multilayer, Ferrite, 10 µH, 0.11 A, 0.52 ohm, SMD"
L7: "Inductor, Shielded Drum Core, Ferrite, 180 µH, 0.27 A, 2.5 ohm, SMD"
Logo2: library part Pb-Free
Logo3: library part FCC_disclaimer, "FCC_disclaimer"
Q1 Q3: library part "BC55-16PA,115, NXP Semiconductor", "Transistor, NPN, 60 V, 1 A, AEC-Q101, SOT1061"
Q2: library part "MMSTA06-7-F, Diodes Inc.", "Transistor, NPN, 80 V, 0.5 A, SOT-323"
R1 R2: "RES, 470, 5%, 0.063 W, 0402"
R3 R4: "RES, 10.0 k, 1%, 0.063 W, 0402"
R5 R21: "RES, 47.5 k, 1%, 0.063 W, 0402"
R6 R8 R11: "RES, 0, 5%, 0.1 W, 0603"
R7: "RES, 200, 1%, 0.25 W, 1206"
R9: "RES, 24.9 k, 1%, 0.1 W, 0603"
R10: "RES, 49.9, 1%, 0.25 W, 1206"
R12: "RES, 100, 1%, 0.1 W, 0603"
R13: "RES, 20.0, 1%, 0.1 W, 0603"
R14: "RES, 1.0 M, 5%, 0.063 W, 0402"
R15: "RES, 2.00 M, 1%, 0.063 W, 0402"
R16: "RES, 499 k, 1%, 0.063 W, 0402"
R17: "RES, 357 k, 1%, 0.063 W, 0402"
R18: "RES, 100 k, 1%, 0.063 W, 0402"
R19: "RES, 294 k, 1%, 0.063 W, 0402"
R20: "RES, 34.0 k, 1%, 0.063 W, 0402"
R22 R23 R24: "RES, 0, 5%, 0.063 W, 0402"
S1: "Switch, Tactile, SPST, 12 V, SMD"
SH-J1 SH-J2 SH-J3 SH-J4 SH-J5 SH-J6: "Shunt, 100mil, Gold plated, Black"
TP1 TP2 TP3: "Test Point, Miniature, SMT"
U1: "Low Power, High Accuracy Digital Humidity Sensor with Temperature Sensor, DMB0006A"
U2: "2.45 GHz Antenna, EIA 1210, Detuning resilient, Edge Mount, SMD"
U3: "Ultra low-power ARM Cortex M3 2.4 GHz Radio MCU, Multi-Protocol, RSHB032E"
U4: "16-bit SPI Programmable DAC for 4-20mA Loops, RGH0016A"
U5: "3.0-V to 65-V Input, 150-mA Output, Ultra-Low Quiescent (ULQ) Synchronous Step-Down Voltage Regulator, DRC0010J"
U6: "Single Output High PSRR LDO, 150 mA, Fixed 2.8 V Output, 2.5 to 6.5 V Input, with Low IQ, 6-pin WSON (DSE), -40 to 85 degC, Green (RoHS & no Sb/Br)"
Y1: "Crystal, 24 MHz, 9 pF, SMD"
Y2: "Crystal, 32.768kHz, 12.5pF, SMD"
ZZ1: library part AssemblyNoteLabel
ZZ2 ZZ3 ZZ4: library part AssemblyNote

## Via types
v1: diameter 34, hole 16, Layer 1 - Top Layer to Layer 4 - Bottom Layer, tented top, 127 vias
v2: diameter 19.68, hole 7.87, Layer 1 - Top Layer to Layer 4 - Bottom Layer, 20 vias
v3: diameter 45, hole 16, Layer 1 - Top Layer to Layer 4 - Bottom Layer, 2 vias

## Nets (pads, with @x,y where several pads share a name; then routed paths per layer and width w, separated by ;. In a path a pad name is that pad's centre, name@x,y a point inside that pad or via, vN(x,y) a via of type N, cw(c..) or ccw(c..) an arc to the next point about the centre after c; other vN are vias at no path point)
CLK: U3.26 U4.4 | length 562
  Layer 1 - Top Layer w8: U3.26@613.07,732.32 638.51,732.32 901.14,469.69 U4.4@901.14,304.53
CS: U3.24 U4.6 | length 488.8
  Layer 1 - Top Layer w8: U3.24@587.48,687.05 587.48,678.52 592.63,673.37 646.91,673.37 856.34,463.94 856.34,405 836.18,384.84 U4.6@836.18,349.8
DCDC_SW: L2.1 U3.17 | length 119.3
  Layer 1 - Top Layer w10: 449.68,674.68 U3.17@449.68,687.05
  Layer 1 - Top Layer w12: L2.1@365.43,620 385.28,639.84 414.84,639.84 449.68,674.68
ERRLVL: J6.2 U4.10 | length 321.3
  Layer 1 - Top Layer w10: v1(680,285) 751.38,285 U4.10@751.54,284.84
  Layer 4 - Bottom Layer w10: J6.2@560,85 560,165 v1(680,285)
GND: C1.2 C2.2 C3.2 C4.2 C5.2 C6.2 C7.2 C8.2 C9.2 C10.2 C11.1 C12.2 C13.2 C14.2 C16.2 C17.2 C18.2 C19.2 C22.2 C23.2 C25.2 C26.2 C27.2 C28.2 C29.2 C30.2 C31.2 C32.2 C33.2 C34.2 C35.2 C36.2 D1.1 D2.1 FL1.2 FL1.5 FL1.6 J1.2 J2.3 J2.5 J2.9 J5.1 J5.2 J6.3 J12.1 J12.2 R13.1 R18.1 R19.1 R20.1 S1.2 U1.2 U2.2 U2.3 U2.4 U3.33 U4.1 U4.2 U4.17 U5.5 U5.10 U5.11 U6.2 Y1.2 Y1.4 | length 2195.8
  Layer 1 - Top Layer w8: v1(45,1010) 73.5,1038.5 D2.1@73.5,1060 ; D1.1@73.5,1130 v1(73.5,1171.5) ; v1(105,940) S1.2@105,992.95 ; v1(618.62,463.62) C32.2@618.62,500 ; v2(826.34,275) 836.18,265.16 U4.17@855.87,245.47
  Layer 1 - Top Layer w10: 104,1045 104,993.95 S1.2@105,992.95 ; FL1.2@560.76,986.02 FL1.5@593.24,986.02 ; v1(610,285) 650,245 C25.2@656.38,245 ; U4.17@836.18,265.16 U4.2@901.14,265.16 ; U4.17@855.87,245.47 U4.1@901.14,245.47 ; v1(1170,910) C29.2@1207.76,910 ; U6.2@1254.21,985.32 1296.97,985.32 v1(1296.97,1010)
  Layer 1 - Top Layer w20: v1(210,770) 263.58,770 C16.2@267.56,766.02 ; v1(220,1022) C6.2@220,1061.38 ; v1(244.05,816.02) C3.2@285.43,816.02 ; v1(359,485) C7.2@359,540 ; U1.2@379.17,1111.02 v1(414.06,1111.02) ; C12.2@462.06,1115.52 v1(462.06,1164.95) ; C5.2@468.62,600 v1(510,600) ; v1(510,485) C4.2@510,540 ; C11.1@517,1115.5 v1(517,1164.92) ; C9.2@662,943.62 v1(662,992.13) ; C10.2@705,978.62 v1(705,1027.13) ; C2.2@752.68,721.02 760,728.35 v1(760,765) ; C8.2@752.68,806.02 v1(794.06,806.02) ; v1@773,35 C23.2@773,81.38 ; C13.2@790,986.5 v1(790,1035) ; C1.2@805,716.5 v1(805,765) ; v1(815,37) C22.2@815,81.38 ; C19.2@856,81.38 856,38 v1(857,37) ; C17.2@897,81.38 897,39 v1(899,37) ; v1(920,770) 920,818.5 C14.2@921.5,820 ; Y1.2@926.5,978.31 v1(926.5,1026.81) ; C18.2@1008.62,285 1025,301.38 v1(1025,325) ; v1(1012.83,38.62) R13.1@1012.83,85 ; R19.1@1075,1430.74 R19.1@1075,1431.38 ; v1(1110,1015) 1154.53,1015 C28.2@1155.59,1013.94 ; C27.2@1149.05,1357.4 C26.2@1249.88,1357.4 ; v1(1160,1060) 1206.65,1060 C30.2@1206.97,1060.32 ; R18.1@1375.59,1512.4 v1(1417.96,1512.4) ; C31.2@1375.62,1554 1401,1554 v1(1417,1570)
  Layer 1 - Top Layer w23: v1@217.41,1588.59 U2.2@274.94,1588.59 ; v1@220.09,1537.41 U2.3@274.94,1537.41 ; U2.4@393.06,1537.41 C34.2@455.03,1537.41 ; R20.1@1293.62,1595 1295.62,1597 v3(1351,1597)
  other v1: 773,37 802,874 703,1080 580,1120 604,1173 733,1173 737.81,1260.68 330,1292 272,1310 387,1312 738,1322 1199.96,1327.4 610,1328 1497,1355 455,1358 215,1368 732.38,1387.4 1199.96,1387.4 607,1402 457,1424 220,1438 733,1456 605,1477 439,1494 533,1509 734.25,1510 219.25,1536.57 733,1561 217,1589 710,1605
  other v2: 826.34,233.66 785,275 867.68,275 826.34,316.34 518.58,723.46 460.51,781.54 518.58,781.54 576.65,781.54 518.58,839.61 1211.46,1455 1188.83,1492.4 1234.1,1492.4 1211.46,1529.8
JTAG_TCK: J2.4 U3.14 | length 399.1
  Layer 1 - Top Layer w8: J2.4@120,565 140,565 225,650 225,680 261.75,716.75 363.15,716.75 398.41,752.01 U3.14@424.09,752.01
JTAG_TMS: J2.2 U3.13 | length 386.6
  Layer 1 - Top Layer w8: J2.2@120,615 165,615 205,655 205,685 252.62,732.62 353.74,732.62 392.81,771.69 U3.13@424.09,771.69
LED_GREEN: R1.2 U3.8 | length 171.9
  Layer 1 - Top Layer w8: R1.2@313.62,950 329.94,933.68 400.84,933.68 449.68,884.84 U3.8@449.68,876.02
LED_RED: R2.1 U3.9 | length 136.6
  Layer 1 - Top Layer w8: R2.1@314.65,911.02 313.62,910 350.08,910 409.65,850.43 U3.9@424.09,850.43
LOOP_M: C20.2 C21.2 R11.1 U4.9 | length 1302.8
  Layer 1 - Top Layer w10: v1(717.57,348.25) 717.57,314.69 727.73,304.53 U4.9@751.54,304.53
  Layer 1 - Top Layer w20: v1(1120,560) C20.2@1120,497.09 C21.2@1215,497.09 v1(1287.09,497.09) ; R11.1@1551.5,705 v1(1605,705)
  Layer 4 - Bottom Layer w20: v1(717.57,348.25) 819.4,348.25 909,437.86 909,529 940,560 v1(1120,560) ; v1(1287.09,497.09) 1397.09,497.09 v1(1605,705)
LOOP_P: C20.1 C21.1 D5.1 R6.2 | length 720.3
  Layer 1 - Top Layer w20: D5.1@1120,304.47 C20.1@1120,382.91 C21.1@1215,382.91 v1(1287.91,382.91) v1@1290,380.83 ; v1(1130,735) R6.2@1183.5,735
  Layer 4 - Bottom Layer w20: v1(1130,735) 1195,670 1195,475.83 v1(1287.91,382.91)
NDAC_ERROR: R14.2 U3.15 U4.7 | length 1025.5
  Layer 1 - Top Layer w8: v1(265,675) 290.87,700.87 372.55,700.87 404,732.32 U3.15@424.09,732.32 ; v1(771.38,411.38) R14.2@815,411.38 816.5,409.88 U4.7@816.5,349.8
  Layer 4 - Bottom Layer w8: v1(265,675) 325,735 440,735 480,695 610,695 725,580 725,457.76 v1(771.38,411.38)
NetC6_1: C6.1 J7.2 U1.5 | length 199.1
  Layer 1 - Top Layer w8: C6.1@220,1108.62 220,1111.46 C6.1@220.43,1111.02
  Layer 1 - Top Layer w20: J7.2@175,1240 175,1156.46 C6.1@220,1111.46 ; C6.1@220.43,1111.02 U1.5@268.94,1111.02
NetC15_1: C15.1 D3.2 D4.1 J4.1 | length 460.7
  Layer 1 - Top Layer w20: D3.2@1225,576.69 1238.19,563.5 C15.1@1305,563.5 1305,557.99 D4.1@1430,432.99 ; D4.1@1447.01,450 J4.1@1640,450
NetC15_2: C15.2 D4.2 D6.1 J4.2 | length 442.6
  Layer 1 - Top Layer w20: D6.1@1336.69,705 1305,673.31 C15.2@1305,626.5 1410.51,626.5 D4.2@1430,607.01 1449.01,588 J4.2@1640,588
NetC16_1: C16.1 U3.12 | length 104
  Layer 1 - Top Layer w8: C16.1@330.55,766.02 359.06,766.02 384.41,791.38 U3.12@424.09,791.38
NetC17_1: C17.1 C18.1 C19.1 J10.2 U4.3 U4.15 | length 594.4
  Layer 1 - Top Layer w10: U4.15@836.34,200.04 U4.15@836.18,200.2 836.18,153.21 856,133.39 C19.1@856,128.62 ; C17.1@897,128.62 901.3,128.62 C17.1@901.5,128.43 ; U4.3@901.14,284.84 961.22,284.84 C18.1@961.38,285
  Layer 1 - Top Layer w20: C19.1@856,128.62 C17.1@897,128.62 v1(897,172.24) ; C18.1@961.38,285 961.38,333.38 980,352 J10.2@980,390
  Layer 3 - POWER w20: v1(897,172.24) 980,255.24 J10.2@980,390
NetC22_1: C22.1 U4.14 | length 73.6
  Layer 1 - Top Layer w10: U4.14@816.5,200.2 816.5,133.46 C22.1@821.34,128.62
NetC23_1: C23.1 C24.1 U4.13 | length 172.1
  Layer 1 - Top Layer w10: C24.1@703.62,180 755,128.62 C23.1@773,128.62 773,137 796.81,160.81 U4.13@796.81,200.2
NetC24_2: C24.2 TP3.1 | length 131.7
  Layer 1 - Top Layer w10: TP3.1@535,205 560,180 C24.2@656.38,180
NetC25_1: C25.1 U4.12 | length 48.1
  Layer 1 - Top Layer w10: C25.1@703.62,245 704.09,245.47 U4.12@751.54,245.47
